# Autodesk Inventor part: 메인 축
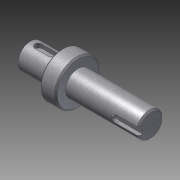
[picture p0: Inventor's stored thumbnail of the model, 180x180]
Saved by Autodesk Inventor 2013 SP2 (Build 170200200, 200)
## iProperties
Created: 2014-10
Part Number: 메인 축
Document SubType Name: Modeling
Designer: KYOUNG IL JANG
Density: 7.86 g/cm^3
Mass: 230.24 g
Surface Area: 74.3518 cm^2
Volume: 29.2926 cm^3
Material: 강철, 연강
Author: SeoGD™ [www.esajin.kr]
Revision Number: 1
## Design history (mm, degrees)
sketch "스케치1"
  geometry: L1 (10.497, -57.5)-(92.497, -57.5); L2 (10.497, -66)-(32.497, -66); L3 (32.497, -72.5)-(46.5, -72.5); L4 (46.5, -66)-(92.497, -66); L5 (92.497, -66)-(92.497, -57.5); L6 (10.497, -66)-(10.497, -57.5); L7 (46.5, -69.749)-(46.5, -45.251) reference; L8 (46.5, -72.5)-(46.5, -66); L9 (32.497, -72.5)-(32.497, -66); L10 (32.497, -35)-(32.497, -80) reference; 2 further points
  constraints: 16 end point, 2 parallel, 2 perpendicular, 2 point on line, 1 collinear, 1 horizontal, 1 midpoint
  dimensions: "d0" = 17 diameter of L4 L1; "d1" = 30 diameter of L3 L1; "d2" = 22 distance of L2.start L2.end; "d5" = 17 diameter of L2 L1; "d19" = 60 distance between parallel lines of L5 L9
revolve "회전1" sketch "스케치1" stored, may be unused: angle "d4" = 90 deg
feature "면 이동2"
chamfer "모따기1" distance "d6" = 1; stored, may be unused: second distance "d7" = 2, angle "d8" = 45 deg
node "작업 평면1"
sketch "스케치2"
  geometry: L1 (-11, -7.5)-(-11, 7.5) reference; L2 (-4.5, 2.5)-(4.5, 2.5); L3 (4.5, -2.5)-(-4.5, -2.5); A1 r 2.5 centre (4.5, 0) between (4.5, -2.5) and (4.5, 2.5); A2 r 2.5 centre (-4.5, 0) between (-4.5, 2.5) and (-4.5, -2.5); 2 further points
  constraints: 4 end point, 4 point on circle, 4 tangent, 2 centre point, 1 horizontal alignment, 1 midpoint, 1 parallel, 1 perpendicular
  dimensions: "d9" = 5 distance between parallel lines of L3 L2; "d10" = 14 dimension on A1 A2; "d11" = 4 distance edge to line of A2 L1
extrude "돌출1" cut sketch "스케치2" distance "d12" = 3; taper "d13" = 0 deg
node "작업 평면2"
sketch "스케치3"
  geometry: L1 (22.998, 7.5)-(22.998, -7.5) reference; L2 (22.998, 2.5)-(7.498, 2.5); L3 (7.498, -2.5)-(22.998, -2.5); A1 r 2.5 centre (7.498, 0) between (7.498, 2.5) and (7.498, -2.5); 2 further points
  constraints: 4 end point, 2 perpendicular, 2 point on circle, 2 point on line, 2 tangent, 1 centre point, 1 horizontal alignment, 1 midpoint
  dimensions: "d14" = 5 distance between parallel lines of L3 L2; "d15" = 18 dimension on A1 L1
extrude "돌출2" cut sketch "스케치3" distance "d16" = 3; taper "d17" = 0 deg
node "솔리드1"
node "참조4"
node "참조5"
